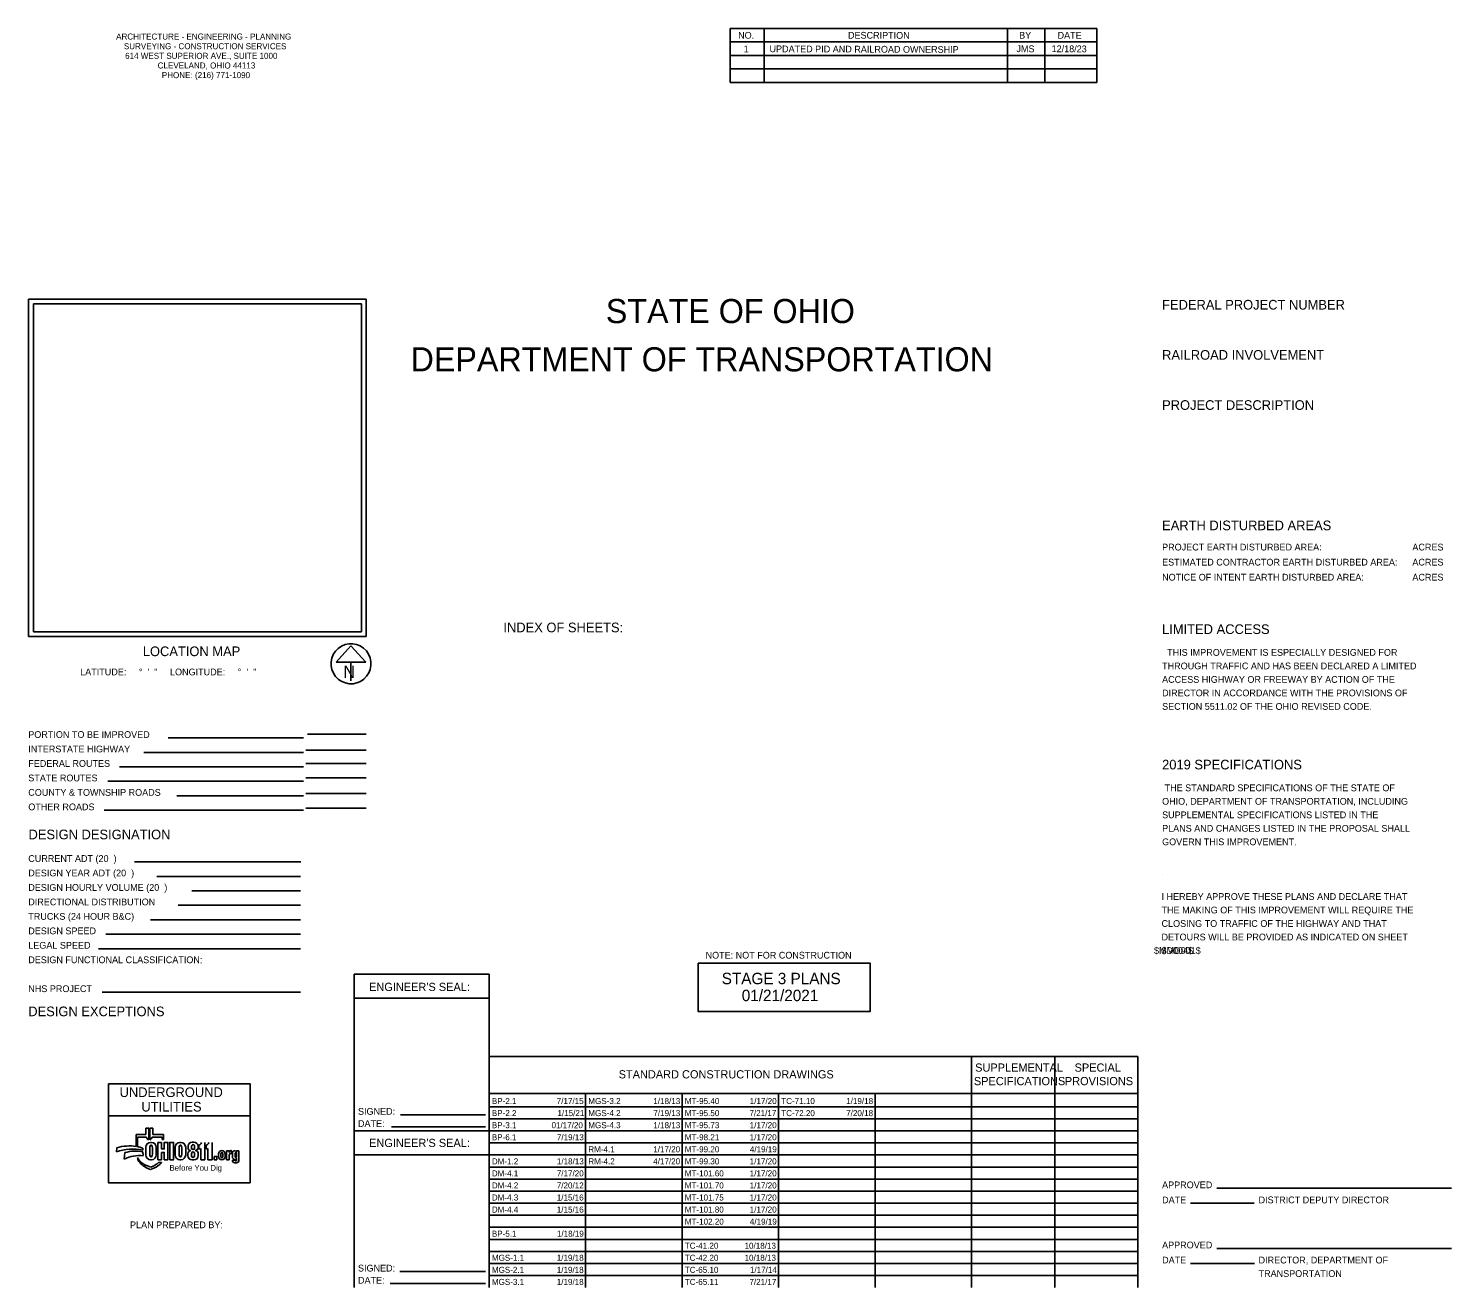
# Model space of a CAD drawing. Extents: x 0 to 96.2, y -27.5 to 31.3.
# Drawn here: x 43.4 to 72.9, y -27.48 to -1.37 of the extents above; entities that cross this region are included whole.
import ezdxf

# ---------------------------------------------------------------- set-up
doc = ezdxf.new("R2010")
doc.units = 0
for name, color, linetype in [('TB1', 7, 'Continuous'), ('TB_PP_50x10_GRID', 7, 'Continuous'), ('TB_SUPER_50x1', 7, 'Continuous'), ('TB_TWOPLAN', 7, 'Continuous')]:
    doc.layers.add(name, color=color, linetype=linetype)

msp = doc.modelspace()

# ---------------------------------------------------------------- linework, layer by layer
at = {"layer": 'TB1'}
for p, q in [((43.403, -6.98), (50.403, -6.98)), ((43.403, -6.98), (43.403, -13.98)), ((43.503, -7.08), (43.503, -13.88)), ((43.503, -7.08), (50.303, -7.08)), ((50.303, -7.08), (50.303, -13.88)), ((50.403, -6.98), (50.403, -13.98)), ((43.403, -13.98), (50.403, -13.98)), ((43.503, -13.88), (50.303, -13.88)), ((50.088, -14.171), (49.78, -14.512)), ((50.395, -14.512), (50.088, -14.171)), ((49.78, -14.512), (50.395, -14.512)), ((50.088, -14.512), (50.088, -14.899)), ((50.088, -14.544), (50.088, -14.544)), ((50.088, -14.544), (50.088, -14.544)), ((49.103, -16.082), (46.297, -16.082)), ((49.186, -16.004), (50.403, -16.004)), ((49.103, -16.382), (45.793, -16.382)), ((50.403, -16.338), (49.153, -16.338)), ((49.103, -16.682), (45.289, -16.682)), ((50.403, -16.61), (49.153, -16.61)), ((49.103, -16.982), (45.048, -16.982)), ((50.403, -16.91), (49.153, -16.91)), ((49.103, -17.282), (46.481, -17.282)), ((50.403, -17.237), (49.153, -17.237)), ((49.103, -17.582), (44.969, -17.582)), ((50.403, -17.537), (49.153, -17.537)), ((49.046, -18.653), (45.597, -18.653)), ((49.04, -18.953), (46.062, -18.953)), ((66.903, -18.919), (66.903, -18.919)), ((49.04, -19.253), (46.788, -19.253)), ((49.04, -19.553), (46.502, -19.553)), ((49.04, -19.853), (45.929, -19.853)), ((49.04, -20.153), (45.007, -20.153)), ((49.04, -20.453), (44.852, -20.453)), ((50.153, -24.23), (50.153, -20.98)), ((50.153, -20.98), (52.953, -20.98)), ((52.953, -27.48), (52.953, -20.98)), ((49.04, -21.353), (44.927, -21.353)), ((50.153, -21.48), (52.953, -21.48)), ((52.953, -22.688), (66.403, -22.688)), ((62.953, -27.48), (62.953, -22.688)), ((64.678, -27.48), (64.678, -22.688)), ((66.403, -27.48), (66.403, -22.688)), ((52.953, -23.459), (66.403, -23.459)), ((54.953, -27.48), (54.953, -23.459)), ((56.953, -27.48), (56.953, -23.459)), ((58.953, -27.48), (58.953, -23.459)), ((60.953, -27.48), (60.953, -23.459)), ((52.953, -23.73), (66.403, -23.73)), ((45.06, -23.919), (47.996, -23.919)), ((45.894, -24.178), (45.834, -24.178)), ((45.834, -24.178), (45.834, -24.303)), ((45.894, -24.416), (45.894, -24.178)), ((45.978, -24.178), (45.918, -24.178)), ((45.918, -24.178), (45.918, -24.416)), ((45.978, -24.303), (45.978, -24.178)), ((50.925, -24.149), (52.874, -24.149)), ((51.111, -23.897), (52.874, -23.897)), ((52.953, -23.98), (66.403, -23.98)), ((45.834, -24.303), (45.637, -24.303)), ((45.637, -24.303), (45.637, -24.555)), ((45.665, -24.559), (45.665, -24.361)), ((45.665, -24.361), (45.846, -24.361)), ((45.952, -24.469), (45.933, -24.469)), ((45.966, -24.361), (46.175, -24.361)), ((46.202, -24.303), (45.978, -24.303)), ((46.161, -24.471), (46.085, -24.471)), ((46.085, -24.471), (46.085, -24.83)), ((46.175, -24.361), (46.175, -24.409)), ((46.175, -24.409), (46.202, -24.409)), ((46.202, -24.409), (46.202, -24.303)), ((46.561, -24.469), (46.543, -24.469)), ((46.832, -24.465), (46.796, -24.465)), ((47.061, -24.471), (47.061, -24.83)), ((47.211, -24.471), (47.211, -24.83)), ((50.153, -27.48), (50.153, -24.23)), ((50.153, -24.23), (52.953, -24.23)), ((52.953, -24.23), (66.403, -24.23)), ((52.953, -24.48), (66.403, -24.48)), ((45.235, -24.58), (45.224, -24.668)), ((45.4, -24.682), (45.384, -24.817)), ((45.775, -24.631), (45.775, -24.588)), ((45.782, -24.744), (45.775, -24.665)), ((45.833, -24.57), (45.833, -24.729)), ((45.915, -24.716), (45.915, -24.579)), ((45.971, -24.579), (45.971, -24.716)), ((46.052, -24.729), (46.052, -24.57)), ((46.161, -24.83), (46.161, -24.678)), ((46.442, -24.57), (46.442, -24.729)), ((46.524, -24.716), (46.524, -24.579)), ((46.58, -24.579), (46.58, -24.716)), ((46.662, -24.729), (46.662, -24.57)), ((46.706, -24.705), (46.706, -24.743)), ((46.71, -24.55), (46.71, -24.577)), ((46.782, -24.75), (46.782, -24.704)), ((46.784, -24.59), (46.784, -24.546)), ((46.845, -24.546), (46.845, -24.59)), ((46.845, -24.704), (46.845, -24.75)), ((46.918, -24.577), (46.918, -24.55)), ((46.923, -24.743), (46.923, -24.705)), ((46.935, -24.606), (46.935, -24.53)), ((46.972, -24.83), (46.972, -24.596)), ((47.086, -24.606), (47.086, -24.53)), ((47.122, -24.83), (47.122, -24.596)), ((47.342, -24.761), (47.342, -24.71)), ((47.392, -24.762), (47.392, -24.71)), ((47.428, -24.71), (47.428, -24.762)), ((47.479, -24.71), (47.479, -24.761)), ((47.563, -24.647), (47.508, -24.647)), ((47.508, -24.647), (47.508, -24.83)), ((47.563, -24.682), (47.563, -24.647)), ((47.563, -24.83), (47.563, -24.734)), ((47.6, -24.697), (47.609, -24.697)), ((47.609, -24.641), (47.604, -24.641)), ((47.609, -24.697), (47.609, -24.641)), ((47.63, -24.771), (47.63, -24.693)), ((47.684, -24.76), (47.684, -24.703)), ((47.716, -24.681), (47.716, -24.646)), ((47.716, -24.646), (47.765, -24.646)), ((47.716, -24.703), (47.716, -24.76)), ((47.765, -24.646), (47.765, -24.84)), ((50.153, -24.73), (52.953, -24.73)), ((52.953, -24.73), (66.403, -24.73)), ((45.664, -24.785), (45.668, -24.805)), ((45.939, -24.981), (45.872, -24.958)), ((45.89, -25.015), (45.932, -25.033)), ((45.932, -25.033), (46.003, -25.002)), ((45.933, -24.83), (45.952, -24.83)), ((45.985, -24.961), (45.939, -24.981)), ((46.085, -24.83), (46.161, -24.83)), ((46.159, -24.89), (46.095, -24.89)), ((46.157, -24.892), (46.159, -24.89)), ((46.543, -24.83), (46.561, -24.83)), ((46.797, -24.834), (46.832, -24.834)), ((47.061, -24.83), (46.972, -24.83)), ((47.211, -24.83), (47.122, -24.83)), ((47.508, -24.83), (47.563, -24.83)), ((47.63, -24.84), (47.684, -24.84)), ((47.713, -24.892), (47.682, -24.892)), ((47.716, -24.84), (47.716, -24.788)), ((52.953, -24.98), (66.403, -24.98)), ((52.953, -25.23), (66.403, -25.23)), ((52.953, -25.48), (66.403, -25.48)), ((68.038, -25.42), (72.903, -25.42)), ((52.953, -25.73), (66.403, -25.73)), ((67.494, -25.732), (68.811, -25.732)), ((52.953, -25.98), (66.403, -25.98)), ((52.953, -26.23), (66.403, -26.23)), ((52.953, -26.48), (66.403, -26.48)), ((52.953, -26.73), (66.403, -26.73)), ((68.038, -26.668), (72.903, -26.668)), ((52.953, -26.98), (66.403, -26.98)), ((67.494, -26.98), (68.817, -26.98)), ((50.897, -27.399), (52.874, -27.399)), ((51.104, -27.147), (52.874, -27.147)), ((52.953, -27.23), (66.403, -27.23))]:
    msp.add_line(p, q, dxfattribs=at)
for points in [[(57.282, -20.753), (60.852, -20.753), (60.852, -21.752), (57.282, -21.752)], [(45.06, -23.254), (47.996, -23.254), (47.996, -25.305), (45.06, -25.305)], [(47.255, -24.762), (47.304, -24.762), (47.304, -24.83), (47.255, -24.83)]]:
    msp.add_lwpolyline(points, close=True, dxfattribs=at)
for points in [[(46.161, -24.678), (46.218, -24.678), (46.218, -24.83), (46.294, -24.83), (46.294, -24.471), (46.218, -24.471), (46.218, -24.606), (46.161, -24.606), (46.161, -24.471)], [(46.332, -24.83), (46.41, -24.83), (46.41, -24.471), (46.332, -24.471), (46.332, -24.83)], [(46.771, -24.64), (46.771, -24.64)], [(46.858, -24.64), (46.858, -24.64)]]:
    msp.add_lwpolyline(points, dxfattribs=at)
for centre, radius, start, end in [((50.088, -14.544), 0.415, 129.7798, 129.7633), ((45.933, -24.57), 0.1, 90, 180), ((45.948, -24.32), 0.111, 201.9296, 240.7469), ((45.864, -24.32), 0.111, 299.2531, 338.0704), ((45.952, -24.57), 0.1, 0, 90), ((46.543, -24.57), 0.1, 90, 180), ((46.561, -24.57), 0.1, 0, 90), ((46.796, -24.55), 0.0856, 90, 180), ((46.832, -24.55), 0.0856, 0, 90), ((46.897, -24.438), 0.0993, 292.5572, 340.7355), ((47.048, -24.438), 0.0993, 292.5572, 340.7355), ((45.564, -25.61), 1.001, 77.8238, 109.8274), ((45.493, -25.462), 0.919, 81.0007, 106.3144), ((45.706, -25.454), 0.713, 83.8248, 116.8021), ((45.625, -25.472), 0.822, 79.44, 105.8467), ((45.493, -25.462), 0.919, 72.1402, 79.2074), ((45.933, -24.729), 0.1, 180, 270), ((45.952, -24.729), 0.1, 270, 0), ((46.543, -24.729), 0.1, 180, 270), ((46.561, -24.729), 0.1, 270, 0), ((46.771, -24.705), 0.065, 90, 180), ((46.797, -24.743), 0.0909, 180, 270), ((46.773, -24.577), 0.0628, 180, 268.1442), ((46.832, -24.743), 0.0909, 270, 0), ((46.855, -24.577), 0.0628, 272.2058, 0), ((46.858, -24.705), 0.065, 0, 90), ((46.926, -24.507), 0.0993, 275.1733, 297.0931), ((47.077, -24.507), 0.0993, 275.1733, 297.0931), ((47.413, -24.71), 0.0718, 92.5886, 180), ((47.413, -24.761), 0.0718, 180, 267.4114), ((47.407, -24.71), 0.0718, 0, 87.4114), ((47.407, -24.761), 0.0718, 272.5886, 0), ((47.604, -24.682), 0.0412, 90, 180), ((47.6, -24.734), 0.037, 90, 180), ((47.682, -24.693), 0.0515, 92.6865, 180), ((47.682, -24.771), 0.052, 180, 265.7132), ((47.677, -24.681), 0.0394, 0, 86.9262), ((45.875, -24.704), 0.225, 201.0457, 232.5314), ((45.826, -24.778), 0.161, 189.6817, 216.0884), ((45.976, -24.668), 0.347, 216.0884, 235.7167), ((46.091, -24.422), 0.581, 232.5314, 241.794), ((46.163, -24.394), 0.678, 235.7167, 246.2325), ((45.995, -24.6), 0.378, 241.794, 250.9821), ((45.824, -24.59), 0.404, 293.4582, 312.0712), ((45.824, -24.59), 0.45, 293.4582, 317.8286), ((47.682, -24.84), 0.0525, 180, 270), ((47.681, -24.788), 0.0351, 264.7825, 0), ((47.713, -24.84), 0.0525, 270, 0)]:
    msp.add_arc(centre, radius, start, end, dxfattribs=at)
for centre, major_axis, ratio, start_param, end_param in [((45.943, -24.579), (0, 0.0543), 0.514403, 4.712389, 7.853982), ((45.943, -24.716), (0, 0.0543), 0.514403, 1.570796, 4.712389), ((46.552, -24.579), (0, 0.0543), 0.514403, 4.712389, 7.853982), ((46.552, -24.716), (0, 0.0543), 0.514403, 1.570796, 4.712389), ((46.814, -24.704), (0, 0.0402), 0.794529, 4.712389, 7.853982), ((46.814, -24.75), (0.0319, 0), 0.959837, 3.141593, 6.283185), ((46.815, -24.546), (0.0304, 0), 0.969373, 0, 3.141593), ((46.815, -24.59), (0.0304, 0), 0.818453, 3.141593, 6.283185), ((47.41, -24.71), (0, 0.0326), 0.553236, 4.712389, 7.853982), ((47.41, -24.762), (0, 0.0346), 0.522014, 1.570796, 4.712389), ((47.7, -24.703), (0, 0.0206), 0.777179, 4.712389, 7.853982), ((47.7, -24.76), (0, 0.0206), 0.777179, 1.570796, 4.712389), ((47.7, -24.84), (0.016, 0), 0.959012, 3.141593, 6.283185)]:
    msp.add_ellipse(centre, major_axis=major_axis, ratio=ratio, start_param=start_param, end_param=end_param, dxfattribs=at)
at = {"layer": 'TB_TWOPLAN'}
for p, q in [((57.949, -1.37), (65.549, -1.37)), ((57.949, -1.37), (57.949, -2.49)), ((58.655, -1.37), (58.655, -2.49)), ((63.701, -1.37), (63.701, -2.49)), ((64.474, -1.37), (64.474, -2.49)), ((65.549, -1.37), (65.549, -2.49)), ((57.949, -1.65), (65.549, -1.65)), ((57.949, -1.93), (65.549, -1.93)), ((57.949, -2.21), (65.549, -2.21)), ((57.949, -2.49), (65.549, -2.49))]:
    msp.add_line(p, q, dxfattribs=at)

# ---------------------------------------------------------------- texts
at = {"layer": 'TB1'}
for s, height, p in [('PROJECT DESCRIPTION', 0.2, (66.903, -9.279)), ('EARTH DISTURBED AREAS', 0.2, (66.903, -11.775)), ('PROJECT EARTH DISTURBED AREA:', 0.14, (66.903, -12.195)), ('     ACRES', 0.14, (71.831, -12.195)), ('ESTIMATED CONTRACTOR EARTH DISTURBED AREA:', 0.14, (66.903, -12.507)), ('     ACRES', 0.14, (71.831, -12.507)), ('NOTICE OF INTENT EARTH DISTURBED AREA:', 0.14, (66.903, -12.819)), ('     ACRES', 0.14, (71.831, -12.819)), ('INDEX OF SHEETS:', 0.2, (53.248, -13.891)), ('LIMITED ACCESS', 0.2, (66.903, -13.927)), ('LOCATION MAP', 0.2, (45.772, -14.386)), ('  THIS IMPROVEMENT IS ESPECIALLY DESIGNED FOR', 0.14, (66.903, -14.379)), ('LATITUDE:     °  \'  "     LONGITUDE:     °  \'  "', 0.14, (44.474, -14.784)), ('N', 0.25, (49.932, -14.836)), ('THROUGH TRAFFIC AND HAS BEEN DECLARED A LIMITED', 0.14, (66.903, -14.659)), ('ACCESS HIGHWAY OR FREEWAY BY ACTION OF THE', 0.14, (66.903, -14.939)), ('DIRECTOR IN ACCORDANCE WITH THE PROVISIONS OF', 0.14, (66.903, -15.219)), ('SECTION 5511.02 OF THE OHIO REVISED CODE.', 0.14, (66.903, -15.499)), ('PORTION TO BE IMPROVED', 0.14, (43.398, -16.082)), ('INTERSTATE HIGHWAY', 0.14, (43.398, -16.382)), ('FEDERAL ROUTES', 0.14, (43.398, -16.682)), ('2019 SPECIFICATIONS', 0.2, (66.903, -16.735)), ('STATE ROUTES', 0.14, (43.398, -16.982)), (' THE STANDARD SPECIFICATIONS OF THE STATE OF', 0.14, (66.903, -17.187)), ('COUNTY & TOWNSHIP ROADS', 0.14, (43.398, -17.282)), ('OHIO, DEPARTMENT OF TRANSPORTATION, INCLUDING', 0.14, (66.903, -17.467)), ('OTHER ROADS', 0.14, (43.398, -17.582)), ('SUPPLEMENTAL SPECIFICATIONS LISTED IN THE', 0.14, (66.903, -17.747)), ('DESIGN DESIGNATION', 0.2, (43.403, -18.184)), ('PLANS AND CHANGES LISTED IN THE PROPOSAL SHALL', 0.14, (66.903, -18.027)), ('GOVERN THIS IMPROVEMENT.', 0.14, (66.903, -18.307)), ('CURRENT ADT (20  )', 0.14, (43.398, -18.653)), ('DESIGN YEAR ADT (20  )', 0.14, (43.398, -18.953)), ('DESIGN HOURLY VOLUME (20  )', 0.14, (43.398, -19.253)), ('DIRECTIONAL DISTRIBUTION', 0.14, (43.398, -19.553)), ('I HEREBY APPROVE THESE PLANS AND DECLARE THAT ', 0.14, (66.891, -19.441)), ('TRUCKS (24 HOUR B&C)', 0.14, (43.398, -19.853)), ('THE MAKING OF THIS IMPROVEMENT WILL REQUIRE THE ', 0.14, (66.891, -19.721)), ('DESIGN SPEED', 0.14, (43.398, -20.153)), ('CLOSING TO TRAFFIC OF THE HIGHWAY AND THAT ', 0.14, (66.891, -20.001)), ('LEGAL SPEED', 0.14, (43.398, -20.453)), ('DETOURS WILL BE PROVIDED AS INDICATED ON SHEET', 0.14, (66.891, -20.281)), ('DESIGN FUNCTIONAL CLASSIFICATION:', 0.14, (43.398, -20.753)), ('$MD004$', 0.14, (66.735, -20.561)), ('$MD001$', 0.14, (66.891, -20.561)), ('   -   .', 0.14, (66.891, -20.561)), ('NHS PROJECT', 0.14, (43.398, -21.353)), ('STAGE 3 PLANS', 0.23712, (57.773, -21.189)), ('01/21/2021', 0.2371, (58.189, -21.54)), ('DESIGN EXCEPTIONS', 0.2, (43.398, -21.853)), ('STANDARD CONSTRUCTION DRAWINGS', 0.17, (55.637, -23.143)), ('SUPPLEMENTAL', 0.17, (63.027, -23.003)), ('SPECIAL', 0.17, (65.089, -23.003)), ('SPECIFICATIONS', 0.17, (63.001, -23.283)), ('PROVISIONS', 0.17, (64.887, -23.283)), ('UNDERGROUND', 0.2, (45.291, -23.529)), ('UTILITIES', 0.2, (45.743, -23.829)), ('SIGNED:', 0.14, (50.233, -23.897)), ('DATE:', 0.14, (50.233, -24.149)), ('Before You Dig', 0.12, (46.326, -25.057)), ('APPROVED', 0.14, (66.903, -25.42)), ('DATE', 0.14, (66.903, -25.732)), ('PLAN PREPARED BY:', 0.14, (45.508, -26.249)), ('APPROVED', 0.14, (66.903, -26.668)), ('DATE', 0.14, (66.903, -26.98)), ('SIGNED:', 0.14, (50.233, -27.147)), ('DATE:', 0.14, (50.233, -27.399))]:
    msp.add_text(s, height=height, dxfattribs=at).set_placement(p)
at = {"layer": 'TB_PP_50x10_GRID'}
for s, height, p in [('STATE OF OHIO', 0.5, (55.371, -7.48)), ('FEDERAL PROJECT NUMBER', 0.2, (66.903, -7.199)), ('DEPARTMENT OF TRANSPORTATION', 0.5, (51.323, -8.48)), ('RAILROAD INVOLVEMENT', 0.2, (66.903, -8.239)), ("ENGINEER'S SEAL:", 0.17, (50.463, -21.33)), ('BP-2.1', 0.125, (53.008, -23.675)), ('7/17/15', 0.125, (54.353, -23.675)), ('MGS-3.2', 0.125, (55.008, -23.675)), ('1/18/13', 0.125, (56.356, -23.675)), ('MT-95.40', 0.125, (57.008, -23.675)), ('1/17/20', 0.125, (58.354, -23.675)), ('TC-71.10', 0.125, (59.008, -23.675)), ('1/19/18', 0.125, (60.354, -23.675)), ('BP-2.2', 0.125, (53.008, -23.925)), ('1/15/21', 0.125, (54.368, -23.925)), ('MGS-4.2', 0.125, (55.008, -23.925)), ('7/19/13', 0.125, (56.356, -23.925)), ('MT-95.50', 0.125, (57.008, -23.925)), ('7/21/17', 0.125, (58.348, -23.925)), ('TC-72.20', 0.125, (59.008, -23.925)), ('7/20/18', 0.125, (60.354, -23.925)), ('BP-3.1', 0.125, (53.008, -24.175)), ('01/17/20', 0.125, (54.245, -24.175)), ('MGS-4.3', 0.125, (55.008, -24.175)), ('1/18/13', 0.125, (56.356, -24.175)), ('MT-95.73', 0.125, (57.008, -24.175)), ('1/17/20', 0.125, (58.354, -24.175)), ("ENGINEER'S SEAL:", 0.17, (50.463, -24.565)), ('BP-6.1', 0.125, (53.008, -24.425)), ('7/19/13', 0.125, (54.356, -24.425)), ('MT-98.21', 0.125, (57.008, -24.425)), ('1/17/20', 0.125, (58.354, -24.425)), ('RM-4.1', 0.125, (55.008, -24.675)), ('1/17/20', 0.125, (56.354, -24.675)), ('MT-99.20', 0.125, (57.008, -24.675)), ('4/19/19', 0.125, (58.357, -24.675)), ('DM-1.2', 0.125, (53.008, -24.925)), ('DM-4.1', 0.125, (53.008, -25.175)), ('7/17/20', 0.125, (54.354, -25.175)), ('1/18/13', 0.125, (54.356, -24.925)), ('RM-4.2', 0.125, (55.008, -24.925)), ('4/17/20', 0.125, (56.354, -24.925)), ('MT-99.30', 0.125, (57.008, -24.925)), ('MT-101.60', 0.125, (57.008, -25.175)), ('1/17/20', 0.125, (58.354, -24.925)), ('1/17/20', 0.125, (58.354, -25.175)), ('DM-4.2', 0.125, (53.008, -25.425)), ('7/20/12', 0.125, (54.355, -25.425)), ('MT-101.70', 0.125, (57.008, -25.425)), ('1/17/20', 0.125, (58.354, -25.425)), ('DM-4.3', 0.125, (53.008, -25.675)), ('1/15/16', 0.125, (54.354, -25.675)), ('MT-101.75', 0.125, (57.008, -25.675)), ('1/17/20', 0.125, (58.354, -25.675)), ('DISTRICT DEPUTY DIRECTOR', 0.14, (68.903, -25.732)), ('DM-4.4', 0.125, (53.008, -25.925)), ('1/15/16', 0.125, (54.354, -25.925)), ('MT-101.80', 0.125, (57.008, -25.925)), ('1/17/20', 0.125, (58.354, -25.925)), ('MT-102.20', 0.125, (57.008, -26.175)), ('4/19/19', 0.125, (58.357, -26.175)), ('BP-5.1', 0.125, (53.008, -26.425)), ('1/18/19', 0.125, (54.357, -26.425)), ('TC-41.20', 0.125, (57.008, -26.675)), ('10/18/13', 0.125, (58.247, -26.675)), ('MGS-1.1', 0.125, (53.008, -26.925)), ('1/19/18', 0.125, (54.354, -26.925)), ('TC-42.20', 0.125, (57.008, -26.925)), ('10/18/13', 0.125, (58.247, -26.925)), ('DIRECTOR, DEPARTMENT OF', 0.14, (68.903, -26.98)), ('MGS-2.1', 0.125, (53.008, -27.175)), ('1/19/18', 0.125, (54.354, -27.175)), ('TC-65.10', 0.125, (57.008, -27.175)), ('1/17/14', 0.125, (58.358, -27.175)), ('TRANSPORTATION', 0.14, (68.903, -27.26)), ('MGS-3.1', 0.125, (53.008, -27.425)), ('1/19/18', 0.125, (54.354, -27.425)), ('TC-65.11', 0.125, (57.008, -27.425)), ('7/21/17', 0.125, (58.348, -27.425))]:
    msp.add_text(s, height=height, dxfattribs=at).set_placement(p)
at = {"layer": 'TB_SUPER_50x1'}
for s, height, p in [('ARCHITECTURE - ENGINEERING - PLANNING', 0.125, (45.219, -1.6)), ('SURVEYING - CONSTRUCTION SERVICES', 0.125, (45.379, -1.8)), ('614 WEST SUPERIOR AVE., SUITE 1000', 0.125, (45.405, -2)), ('CLEVELAND, OHIO 44113', 0.125, (46.08, -2.2)), ('PHONE: (216) 771-1090', 0.125, (46.166, -2.4)), ('NOTE: NOT FOR CONSTRUCTION', 0.14, (57.439, -20.658))]:
    msp.add_text(s, height=height, dxfattribs=at).set_placement(p)
at = {"layer": 'TB_TWOPLAN'}
for s, p in [('NO.', (58.113, -1.581)), ('DESCRIPTION', (60.391, -1.58)), ('BY', (63.939, -1.581)), ('DATE', (64.736, -1.581)), ('1', (58.229, -1.863)), ('UPDATED PID AND RAILROAD OWNERSHIP', (58.764, -1.862)), ('JMS', (63.883, -1.861)), ('12/18/23', (64.612, -1.861))]:
    msp.add_text(s, height=0.14, rotation=359.7853, dxfattribs=at).set_placement(p)

doc.saveas('drawing.dxf')
